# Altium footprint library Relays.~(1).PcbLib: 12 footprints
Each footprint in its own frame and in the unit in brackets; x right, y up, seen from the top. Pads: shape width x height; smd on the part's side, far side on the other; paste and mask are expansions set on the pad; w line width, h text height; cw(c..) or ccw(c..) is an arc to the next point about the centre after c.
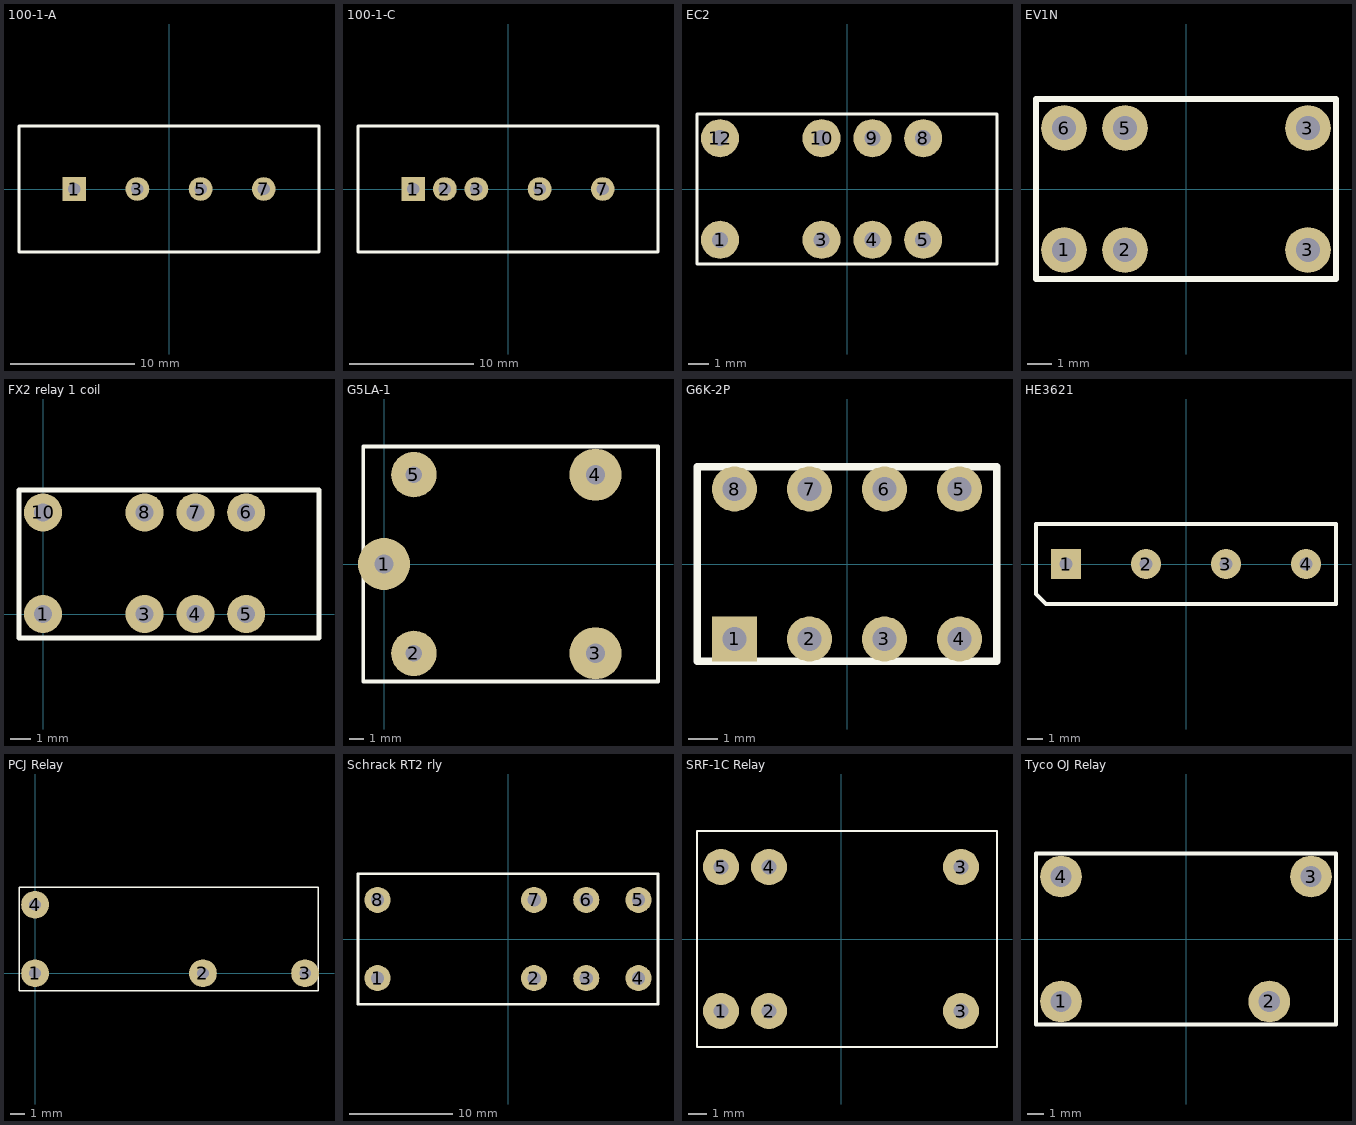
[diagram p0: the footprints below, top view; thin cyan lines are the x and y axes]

## 100-1-A [mm] "Pickering Relay reed relay"
height 12.7
pads (4):
  rect 1.905x1.905 hole 1: 1(-7.62,0)
  round 1.905 hole 1: 3(-2.54,0) 5(2.54,0) 7(7.62,0)
Top Overlay:
  lines w0.254: -12.065,-5.08 -12.065,5.08 12.065,5.08 12.065,-5.08 -12.065,-5.08

## 100-1-C [mm] "Pickering Relay reed relay"
height 12.7
pads (5):
  rect 1.905x1.905 hole 1: 1(-7.62,0)
  round 1.905 hole 1: 2(-5.08,0) 3(-2.54,0) 5(2.54,0) 7(7.62,0)
Top Overlay:
  lines w0.254: -12.065,-5.08 12.065,-5.08 12.065,5.08 -12.065,5.08 -12.065,-5.08

## EC2 [mm] "EC2 series relay"
height 9.4
pads (8):
  round 1.905 hole 0.8: 1(-6.35,-2.54) 3(-1.27,-2.54) 4(1.27,-2.54) 5(3.81,-2.54) 8(3.81,2.54) 9(1.27,2.54) 10(-1.27,2.54) 12(-6.35,2.54)
Top Overlay:
  lines w0.127: -7.5,-3.75 -7.5,3.75 7.5,3.75 7.5,-3.75 -7.5,-3.75

## EV1N [mm] "Sub min relay"
height 10
pads (6):
  round 1.905 hole 1: 1(-5.08,-2.54) 2(-2.54,-2.54) 3(5.08,-2.54) 3(5.08,2.54) 5(-2.54,2.54) 6(-5.08,2.54)
Top Overlay:
  lines w0.254: -6.25,-3.75 -6.25,3.75 6.25,3.75 6.25,-3.75 -6.25,-3.75

## FX2 relay 1 coil [mm] "FX2 relay with 1 coil"
height 13
pads (8):
  round 1.905 hole 0.9: 1(0,0) 3(5.08,0) 4(7.62,0) 5(10.16,0) 6(10.16,5.08) 7(7.62,5.08) 8(5.08,5.08) 10(0,5.08)
Top Overlay:
  lines w0.254: -1.2,-1.2 -1.2,6.2 13.8,6.2 13.8,-1.2 -1.2,-1.2

## G5LA-1 [mm] "10A CO relay"
height 15.8
pads (5):
  round 3.5 hole 1.3: 1(0,0) 3(14.2,-6) 4(14.2,6)
  round 3.048 hole 1.1: 2(2,-6) 5(2,6)
Top Overlay:
  lines w0.254: -1.4,-7.9 18.4,-7.9 18.4,7.9 -1.4,7.9 ; -1.397,-7.874 -1.397,7.874

## G6K-2P [mil] "G6K-2P relay"
height 196.85
pads (8):
  rect 60x60 hole 31.5: 1(-150,-100)
  round 60 hole 31.5: 2(-50,-100) 3(50,-100) 4(150,-100) 5(150,100) 6(50,100) 7(-50,100) 8(-150,100)
Top Overlay:
  lines w10: -200,-130 200,-130 200,130 -200,130 -200,-130

## HE3621 [mm] "Hamlin Reed Relay"
height 7.5
pads (4):
  rect 1.905x1.905 hole 0.8: 1(-7.62,0)
  round 1.905 hole 0.8: 2(-2.54,0) 3(2.54,0) 4(7.62,0)
Top Overlay:
  lines w0.254: -9.525,-1.905 -9.525,2.54 9.525,2.54 9.525,-2.54 -8.89,-2.54 -9.525,-1.905

## PCJ Relay [mm] "TE PCJ PCB relay 3/5A contact 200mW Coil"
height 15
pads (4):
  round 1.905 hole 0.8: 1(0,0) 2(11.5,0) 3(18.5,0) 4(0,4.7)
Top Overlay:
  lines w0.1: -1.1,-1.2 19.4,-1.2 19.4,5.9 -1.1,5.9 -1.1,-1.2

## Schrack RT2 rly [mm] "Schrack RT2 rly, 2 contacts 8A"
height 15.7
pads (8):
  round 2.54 hole 1.3: 1(-12.7,-3.81) 2(2.54,-3.81) 3(7.62,-3.81) 4(12.7,-3.81) 5(12.7,3.81) 6(7.62,3.81) 7(2.54,3.81) 8(-12.7,3.81)
Top Overlay:
  lines w0.254: -14.605,-6.35 -14.605,6.35 14.605,6.35 14.605,-6.35 -14.605,-6.35

## SRF-1C Relay [mm] "IMO SRF-1C relay 1A contact 200mW coil"
height 12.7
pads (6):
  round 1.905 hole 0.8: 1(-6.35,-3.81) 2(-3.81,-3.81) 3(6.35,-3.81) 3(6.35,3.81) 4(-3.81,3.81) 5(-6.35,3.81)
Top Overlay:
  lines w0.1: -7.62,-5.715 8.255,-5.715 8.255,5.715 -7.62,5.715 -7.62,-5.715

## Tyco OJ Relay [mm] "Tyco OJ/OJE relay High isolation contact/coil"
height 14.732
pads (4):
  round 2.54 hole 1.3: 1(-7.62,-3.81) 2(5.08,-3.81) 3(7.62,3.81) 4(-7.62,3.81)
Top Overlay:
  lines w0.254: -9.144,-5.207 -9.144,5.207 9.144,5.207 9.144,-5.207 -9.144,-5.207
